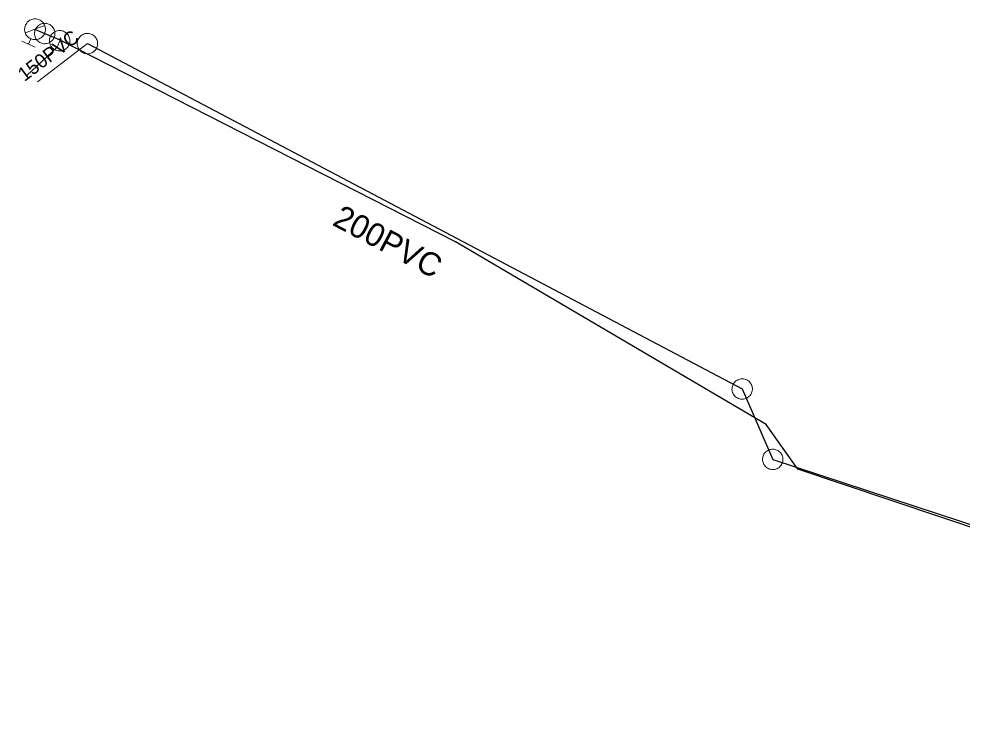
# Model space of a CAD drawing. Extents: x -741806 to -738704, y -1059275 to -1055387.
# Drawn here: x -740458.54 to -740418.07, y -1057165.35 to -1057135.3 of the extents above; entities that cross this region are included whole.
import ezdxf

# ---------------------------------------------------------------- set-up
doc = ezdxf.new("R2010")
doc.units = 0
doc.header["$LTSCALE"] = 0.4
for name, color, linetype, lineweight in [('2', 7, 'Continuous', 25), ('21', 7, 'Continuous', 13), ('3', 7, 'Continuous', 13), ('50', 7, 'Continuous', 13), ('51', 7, 'Continuous', 13), ('52', 7, 'Continuous', 25), ('56', 7, 'Continuous', 13)]:
    doc.layers.add(name, color=color, linetype=linetype, lineweight=lineweight)
doc.layers.add('5', color=7, linetype='Continuous')
doc.layers.add('55', color=7, linetype='Continuous')

msp = doc.modelspace()

# ---------------------------------------------------------------- linework, layer by layer
at = {"layer": '2'}
msp.add_line((-740426.199, -1057154.2), (-740396.239, -1057164.08), dxfattribs=at)
msp.add_lwpolyline([(-740455.6, -1057136.36), (-740427.51, -1057151.179), (-740426.199, -1057154.2)], dxfattribs=at)
at = {"layer": '21'}
msp.add_lwpolyline([(-740456.771, -1057136.215), (-740456.894, -1057136.509), (-740458.199, -1057137.73)], dxfattribs=at)
at = {"layer": '3'}
for points in [[(-740455.252, -1057136.093), (-740455.281, -1057136.06), (-740455.314, -1057136.028), (-740455.351, -1057136), (-740455.389, -1057135.976), (-740455.431, -1057135.956), (-740455.475, -1057135.941), (-740455.519, -1057135.93), (-740455.564, -1057135.924), (-740455.61, -1057135.923), (-740455.655, -1057135.927), (-740455.701, -1057135.935), (-740455.745, -1057135.948), (-740455.787, -1057135.966), (-740455.827, -1057135.987), (-740455.865, -1057136.013), (-740455.9, -1057136.043), (-740455.931, -1057136.076), (-740455.959, -1057136.112), (-740455.983, -1057136.151), (-740456.003, -1057136.193), (-740456.018, -1057136.236), (-740456.029, -1057136.28), (-740456.035, -1057136.326), (-740456.037, -1057136.371), (-740456.033, -1057136.417), (-740456.024, -1057136.462), (-740456.012, -1057136.506), (-740455.994, -1057136.549), (-740455.972, -1057136.589), (-740455.945, -1057136.627), (-740455.916, -1057136.661), (-740455.884, -1057136.692), (-740455.847, -1057136.721), (-740455.807, -1057136.745), (-740455.767, -1057136.764), (-740455.723, -1057136.78), (-740455.679, -1057136.79), (-740455.633, -1057136.796), (-740455.588, -1057136.797), (-740455.542, -1057136.794), (-740455.497, -1057136.786), (-740455.453, -1057136.773), (-740455.41, -1057136.756), (-740455.37, -1057136.734), (-740455.333, -1057136.708), (-740455.297, -1057136.678), (-740455.266, -1057136.645), (-740455.238, -1057136.609), (-740455.215, -1057136.569), (-740455.195, -1057136.528), (-740455.18, -1057136.485), (-740455.168, -1057136.44), (-740455.163, -1057136.395), (-740455.161, -1057136.349), (-740455.165, -1057136.303), (-740455.173, -1057136.258), (-740455.186, -1057136.215), (-740455.204, -1057136.172), (-740455.226, -1057136.132), (-740455.251, -1057136.094)], [(-740427.122, -1057151.383), (-740427.104, -1057151.342), (-740427.089, -1057151.299), (-740427.079, -1057151.254), (-740427.073, -1057151.209), (-740427.073, -1057151.163), (-740427.077, -1057151.117), (-740427.086, -1057151.072), (-740427.099, -1057151.028), (-740427.118, -1057150.987), (-740427.14, -1057150.947), (-740427.166, -1057150.909), (-740427.196, -1057150.874), (-740427.23, -1057150.844), (-740427.266, -1057150.816), (-740427.306, -1057150.792), (-740427.347, -1057150.773), (-740427.391, -1057150.759), (-740427.435, -1057150.748), (-740427.481, -1057150.743), (-740427.527, -1057150.742), (-740427.572, -1057150.747), (-740427.616, -1057150.755), (-740427.661, -1057150.769), (-740427.703, -1057150.786), (-740427.743, -1057150.809), (-740427.78, -1057150.836), (-740427.815, -1057150.865), (-740427.846, -1057150.9), (-740427.873, -1057150.936), (-740427.897, -1057150.976), (-740427.916, -1057151.017), (-740427.931, -1057151.06), (-740427.941, -1057151.105), (-740427.946, -1057151.151), (-740427.947, -1057151.196), (-740427.943, -1057151.242), (-740427.934, -1057151.286), (-740427.92, -1057151.331), (-740427.902, -1057151.372), (-740427.88, -1057151.412), (-740427.854, -1057151.45), (-740427.824, -1057151.485), (-740427.79, -1057151.516), (-740427.754, -1057151.543), (-740427.714, -1057151.566), (-740427.672, -1057151.586), (-740427.629, -1057151.601), (-740427.585, -1057151.611), (-740427.539, -1057151.616), (-740427.493, -1057151.616), (-740427.448, -1057151.612), (-740427.403, -1057151.604), (-740427.359, -1057151.59), (-740427.317, -1057151.572), (-740427.277, -1057151.549), (-740427.239, -1057151.523), (-740427.205, -1057151.493), (-740427.174, -1057151.459), (-740427.146, -1057151.423), (-740427.123, -1057151.384)], [(-740426.025, -1057154.602), (-740425.985, -1057154.581), (-740425.946, -1057154.557), (-740425.91, -1057154.528), (-740425.877, -1057154.496), (-740425.848, -1057154.461), (-740425.822, -1057154.422), (-740425.802, -1057154.382), (-740425.784, -1057154.339), (-740425.773, -1057154.295), (-740425.765, -1057154.25), (-740425.762, -1057154.204), (-740425.764, -1057154.158), (-740425.771, -1057154.113), (-740425.782, -1057154.069), (-740425.798, -1057154.026), (-740425.818, -1057153.984), (-740425.843, -1057153.946), (-740425.871, -1057153.91), (-740425.904, -1057153.878), (-740425.939, -1057153.848), (-740425.977, -1057153.823), (-740426.017, -1057153.802), (-740426.06, -1057153.785), (-740426.104, -1057153.773), (-740426.15, -1057153.765), (-740426.195, -1057153.763), (-740426.241, -1057153.764), (-740426.287, -1057153.771), (-740426.331, -1057153.783), (-740426.374, -1057153.799), (-740426.414, -1057153.819), (-740426.453, -1057153.843), (-740426.489, -1057153.872), (-740426.522, -1057153.905), (-740426.551, -1057153.939), (-740426.577, -1057153.978), (-740426.597, -1057154.018), (-740426.614, -1057154.062), (-740426.626, -1057154.105), (-740426.634, -1057154.15), (-740426.637, -1057154.196), (-740426.635, -1057154.242), (-740426.629, -1057154.287), (-740426.617, -1057154.331), (-740426.601, -1057154.374), (-740426.581, -1057154.415), (-740426.556, -1057154.454), (-740426.528, -1057154.489), (-740426.495, -1057154.522), (-740426.46, -1057154.551), (-740426.421, -1057154.576), (-740426.381, -1057154.598), (-740426.338, -1057154.614), (-740426.295, -1057154.627), (-740426.249, -1057154.635), (-740426.203, -1057154.637), (-740426.158, -1057154.635), (-740426.112, -1057154.629), (-740426.068, -1057154.617), (-740426.026, -1057154.602)]]:
    msp.add_lwpolyline(points, dxfattribs=at)
at = {"layer": '50'}
for p, q in [((-740457.848, -1057135.745), (-740457.43, -1057135.583)), ((-740457.848, -1057135.745), (-740458.262, -1057135.904)), ((-740458.409, -1057136.261), (-740458.128, -1057136.385)), ((-740458.027, -1057136.155), (-740458.128, -1057136.385)), ((-740457.846, -1057136.509), (-740458.128, -1057136.385))]:
    msp.add_line(p, q, dxfattribs=at)
msp.add_lwpolyline([(-740458.253, -1057135.563), (-740458.27, -1057135.609), (-740458.283, -1057135.653), (-740458.29, -1057135.701), (-740458.292, -1057135.747), (-740458.291, -1057135.791), (-740458.282, -1057135.839), (-740458.27, -1057135.883), (-740458.254, -1057135.928), (-740458.234, -1057135.97), (-740458.207, -1057136.008), (-740458.178, -1057136.045), (-740458.146, -1057136.079), (-740458.108, -1057136.107), (-740458.069, -1057136.133), (-740458.028, -1057136.154), (-740457.985, -1057136.17), (-740457.942, -1057136.183), (-740457.895, -1057136.19), (-740457.847, -1057136.192), (-740457.8, -1057136.19), (-740457.755, -1057136.183), (-740457.709, -1057136.171), (-740457.666, -1057136.154), (-740457.625, -1057136.134), (-740457.584, -1057136.108), (-740457.548, -1057136.079), (-740457.516, -1057136.046), (-740457.484, -1057136.01), (-740457.461, -1057135.97), (-740457.437, -1057135.93), (-740457.421, -1057135.885), (-740457.41, -1057135.84), (-740457.402, -1057135.796), (-740457.398, -1057135.747), (-740457.402, -1057135.701), (-740457.408, -1057135.655), (-740457.421, -1057135.611), (-740457.437, -1057135.566), (-740457.459, -1057135.523), (-740457.484, -1057135.486), (-740457.515, -1057135.448), (-740457.548, -1057135.416), (-740457.582, -1057135.386), (-740457.623, -1057135.359), (-740457.664, -1057135.338), (-740457.707, -1057135.322), (-740457.753, -1057135.311), (-740457.799, -1057135.302), (-740457.845, -1057135.3), (-740457.893, -1057135.303), (-740457.938, -1057135.309), (-740457.985, -1057135.321), (-740458.027, -1057135.338), (-740458.068, -1057135.358), (-740458.107, -1057135.386), (-740458.145, -1057135.413), (-740458.178, -1057135.446), (-740458.205, -1057135.483), (-740458.231, -1057135.522)], close=True, dxfattribs=at)
at = {"layer": '51'}
msp.add_lwpolyline([(-740457.832, -1057135.757), (-740457.848, -1057135.8), (-740457.859, -1057135.844), (-740457.866, -1057135.89), (-740457.868, -1057135.935), (-740457.864, -1057135.981), (-740457.857, -1057136.026), (-740457.844, -1057136.07), (-740457.827, -1057136.113), (-740457.805, -1057136.153), (-740457.78, -1057136.191), (-740457.751, -1057136.226), (-740457.718, -1057136.259), (-740457.682, -1057136.287), (-740457.643, -1057136.311), (-740457.602, -1057136.331), (-740457.559, -1057136.347), (-740457.515, -1057136.358), (-740457.47, -1057136.365), (-740457.423, -1057136.366), (-740457.377, -1057136.363), (-740457.333, -1057136.355), (-740457.288, -1057136.343), (-740457.246, -1057136.325), (-740457.206, -1057136.304), (-740457.167, -1057136.278), (-740457.132, -1057136.249), (-740457.101, -1057136.217), (-740457.072, -1057136.18), (-740457.048, -1057136.141), (-740457.027, -1057136.1), (-740457.012, -1057136.058), (-740457.001, -1057136.013), (-740456.994, -1057135.967), (-740456.993, -1057135.922), (-740456.996, -1057135.876), (-740457.003, -1057135.831), (-740457.016, -1057135.787), (-740457.033, -1057135.744), (-740457.055, -1057135.704), (-740457.08, -1057135.666), (-740457.11, -1057135.631), (-740457.142, -1057135.599), (-740457.179, -1057135.571), (-740457.217, -1057135.546), (-740457.258, -1057135.526), (-740457.301, -1057135.51), (-740457.346, -1057135.5), (-740457.391, -1057135.493), (-740457.437, -1057135.491), (-740457.483, -1057135.494), (-740457.528, -1057135.503), (-740457.572, -1057135.514), (-740457.614, -1057135.532), (-740457.655, -1057135.553), (-740457.693, -1057135.579), (-740457.728, -1057135.608), (-740457.759, -1057135.641), (-740457.788, -1057135.677), (-740457.812, -1057135.716)], close=True, dxfattribs=at)
msp.add_lwpolyline([(-740456.958, -1057136.642), (-740456.915, -1057136.658), (-740456.871, -1057136.669), (-740456.825, -1057136.675), (-740456.78, -1057136.677), (-740456.734, -1057136.673), (-740456.689, -1057136.665), (-740456.645, -1057136.652), (-740456.602, -1057136.635), (-740456.563, -1057136.613), (-740456.525, -1057136.587), (-740456.49, -1057136.558), (-740456.457, -1057136.524), (-740456.429, -1057136.488), (-740456.405, -1057136.45), (-740456.386, -1057136.408), (-740456.37, -1057136.365), (-740456.359, -1057136.321), (-740456.353, -1057136.275), (-740456.352, -1057136.229), (-740456.356, -1057136.183), (-740456.364, -1057136.138), (-740456.376, -1057136.094), (-740456.394, -1057136.052), (-740456.415, -1057136.012), (-740456.442, -1057135.974), (-740456.471, -1057135.939), (-740456.504, -1057135.908), (-740456.541, -1057135.879), (-740456.58, -1057135.855), (-740456.621, -1057135.835), (-740456.664, -1057135.82), (-740456.708, -1057135.809), (-740456.754, -1057135.803), (-740456.799, -1057135.802), (-740456.845, -1057135.805), (-740456.89, -1057135.813), (-740456.934, -1057135.826), (-740456.977, -1057135.843), (-740457.016, -1057135.866), (-740457.054, -1057135.891), (-740457.089, -1057135.921), (-740457.122, -1057135.954), (-740457.149, -1057135.99), (-740457.173, -1057136.029), (-740457.193, -1057136.07), (-740457.209, -1057136.113), (-740457.219, -1057136.158), (-740457.226, -1057136.203), (-740457.227, -1057136.249), (-740457.223, -1057136.295), (-740457.215, -1057136.34), (-740457.203, -1057136.384), (-740457.185, -1057136.426), (-740457.164, -1057136.466), (-740457.137, -1057136.504), (-740457.108, -1057136.54), (-740457.075, -1057136.571), (-740457.038, -1057136.599), (-740456.999, -1057136.623), (-740456.959, -1057136.642)], dxfattribs=at)
at = {"layer": '52'}
msp.add_lwpolyline([(-740379.357, -1057170.275), (-740379.52, -1057170.179), (-740394.51, -1057165.29), (-740405.539, -1057161.35), (-740416.989, -1057157.35), (-740425.129, -1057154.62), (-740426.48, -1057152.71), (-740439.809, -1057144.86), (-740456.771, -1057136.215), (-740457.511, -1057135.899), (-740457.85, -1057135.75)], dxfattribs=at)
at = {"layer": '56'}
msp.add_line((-740457.739, -1057138), (-740455.6, -1057136.36), dxfattribs=at)

# ---------------------------------------------------------------- texts
at = {"layer": '5'}
msp.add_text('200PVC', height=1, rotation=332, dxfattribs=at).set_placement((-740445.134, -1057144.125))
at = {"layer": '55'}
msp.add_text('150PVC', height=0.6, rotation=37, dxfattribs=at).set_placement((-740458.299, -1057138.012))

doc.saveas('drawing.dxf')
